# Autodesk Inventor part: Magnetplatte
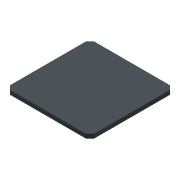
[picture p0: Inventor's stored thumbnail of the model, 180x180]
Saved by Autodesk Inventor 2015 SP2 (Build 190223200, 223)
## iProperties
Created: 2017-07
Material: Fe
Document SubType Name: Modeling
Designer: UR
Density: 7.15 g/cm^3
Appearance: Eisen - grau
Part Number: Magnetplatte
Mass: 2.8457 g
Surface Area: 8.73657 cm^2
Volume: 0.398 cm^3
Author: UR
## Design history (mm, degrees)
sketch "Skizze1"
  geometry: L1 (-10, 10)-(10, 10); L2 (10, 10)-(10, -10); L3 (10, -10)-(-10, -10); L4 (-10, -10)-(-10, 10); L5 (0, 10)-(0, -10); L6 (10, 0)-(-10, 0); 1 further point
  constraints: 12 end point, 6 midpoint, 2 parallel, 2 perpendicular, 1 horizontal
  dimensions: "d0" = 20 distance of L1.start L1.end
extrude "Extrusion1" new body sketch "Skizze1" distance "d1" = 1; taper "d2" = 0 deg
chamfer "Fase1" distance "d3" = 1; stored, may be unused: second distance "d4" = 2, angle "d5" = 45 deg
node "Volumenkörper1"
